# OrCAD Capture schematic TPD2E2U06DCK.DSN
size A; title: TPD2E2U06 Dual-Channel High-Speed ESD Protection Device; rev: 1.0; note: Datasheet: SLLSEG9C    EVM:NA
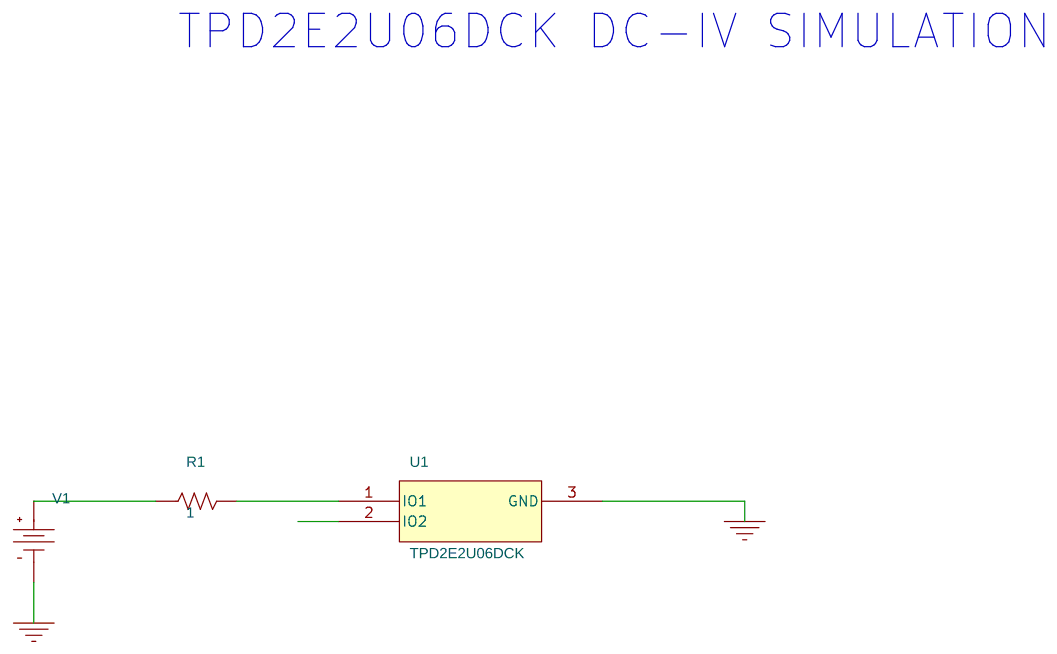
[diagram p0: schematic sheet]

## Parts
R1  1  [AXRC05]
U1  TPD2E2U06DCK
V1  VDC

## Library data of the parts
R1 = R
U1 = TPD2E2U06DCK
V1 = VDC

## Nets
0: U1.3(GND) V1.1(-)
N00192: R1.1 V1.0(+)
N00196: R1.2 U1.1(IO1)

Not connected (* = marked no-connect by the designer): U1 2(IO2)

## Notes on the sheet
- TPD2E2U06DCK DC-IV SIMULATION
